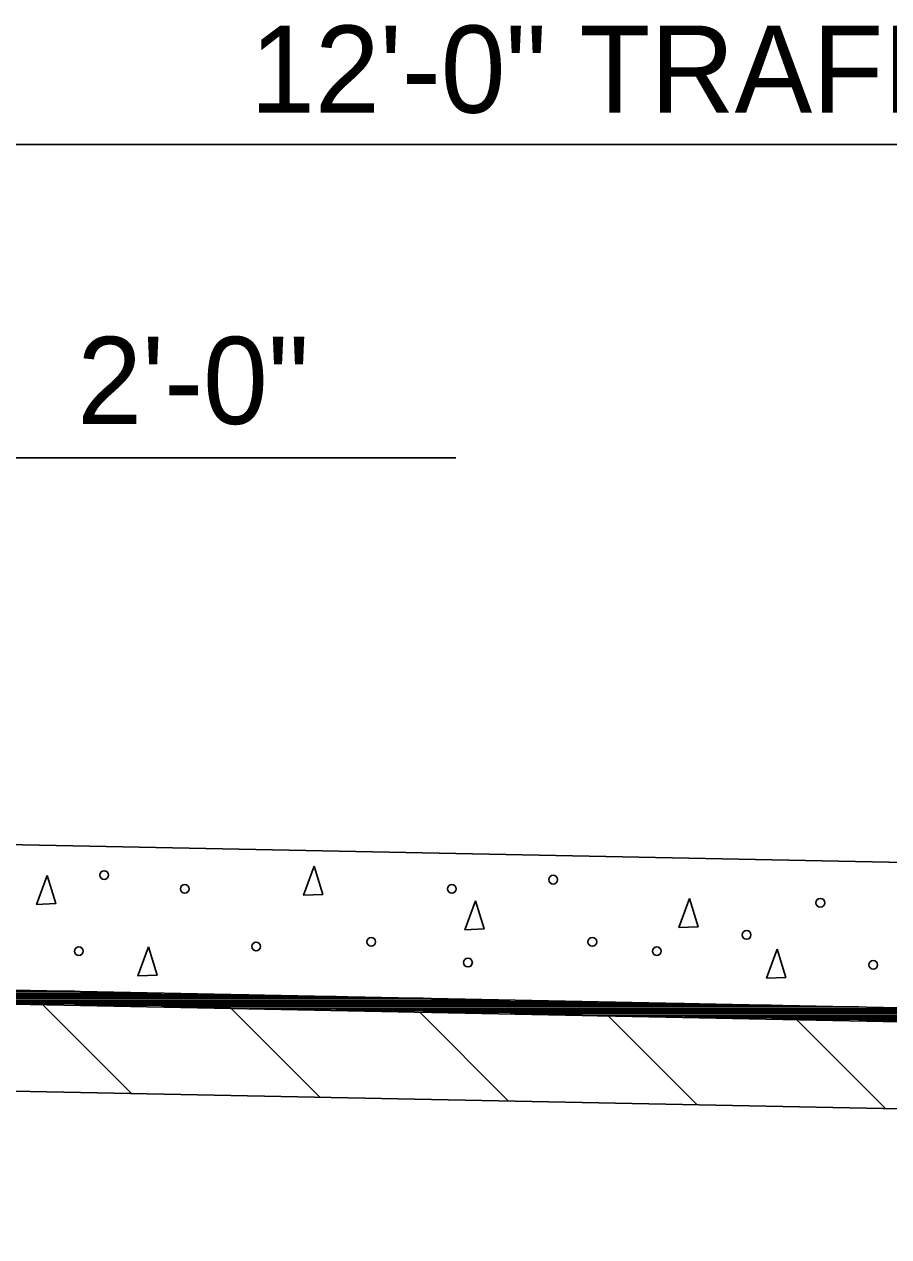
# Model space of a CAD drawing. Extents: x 60325 to 61047, y 53669 to 53767.
# Drawn here: x 60356.12 to 60361.08, y 53739.08 to 53746.03 of the extents above; entities that cross this region are included whole.
import ezdxf

# ---------------------------------------------------------------- set-up
doc = ezdxf.new("R2010")
doc.units = 0
doc.layers.add('R_Border', color=7, linetype='Continuous')
doc.layers.add('R_Border Prem', color=7, linetype='Continuous')

msp = doc.modelspace()

# ---------------------------------------------------------------- linework, layer by layer
at = {"layer": 'R_Border'}
for p, q in [((60367.2467, 53745.3445), (60355.2467, 53745.3445)), ((60358.5934, 53743.5486), (60355.2467, 53743.5486))]:
    msp.add_line(p, q, dxfattribs=at)
msp.add_lwpolyline([(60353.2158, 53741.2633), (60355.2467, 53741.3445), (60381.2467, 53740.8245)], dxfattribs=at)
at = {"layer": 'R_Border Prem'}
for p, q in [((60353.2467, 53740.468), (60357.4066, 53740.468)), ((60353.2467, 53740.458), (60357.9066, 53740.458)), ((60353.5868, 53740.478), (60356.9066, 53740.478)), ((60354.0868, 53740.488), (60356.4066, 53740.488)), ((60355.2467, 53740.5112), (60383.2467, 53739.9512)), ((60353.2467, 53740.448), (60358.4066, 53740.448)), ((60353.2467, 53740.438), (60358.9066, 53740.438)), ((60355.2467, 53740.4312), (60383.2467, 53739.8712)), ((60355.4058, 53740.428), (60359.4066, 53740.428)), ((60355.9058, 53740.418), (60359.9066, 53740.418)), ((60356.2223, 53740.4117), (60356.7326, 53739.9014)), ((60356.4058, 53740.408), (60360.4066, 53740.408)), ((60356.9058, 53740.398), (60360.9066, 53740.398)), ((60357.3046, 53740.39), (60357.8149, 53739.8797)), ((60357.4058, 53740.388), (60361.4066, 53740.388)), ((60357.9058, 53740.378), (60361.9066, 53740.378)), ((60358.3869, 53740.3684), (60358.8972, 53739.8581)), ((60358.4058, 53740.368), (60362.4066, 53740.368)), ((60358.9058, 53740.358), (60362.9066, 53740.358)), ((60359.4058, 53740.348), (60363.4066, 53740.348)), ((60359.4692, 53740.3467), (60359.9795, 53739.8364)), ((60359.9058, 53740.338), (60363.9066, 53740.338)), ((60360.4058, 53740.328), (60364.4066, 53740.328)), ((60360.5515, 53740.3251), (60361.0618, 53739.8148)), ((60360.9058, 53740.318), (60364.9066, 53740.318)), ((60355.2467, 53739.9311), (60397.7927, 53739.0802))]:
    msp.add_line(p, q, dxfattribs=at)
for points in [[(60356.2481, 53741.1523), (60356.1876, 53740.9863), (60356.2976, 53740.9908), (60356.2481, 53741.1523)], [(60357.7812, 53741.2051), (60357.7207, 53741.0391), (60357.8307, 53741.0436), (60357.7812, 53741.2051)], [(60359.9353, 53741.0201), (60359.8748, 53740.8541), (60359.9848, 53740.8586), (60359.9353, 53741.0201)], [(60358.7063, 53741.0069), (60358.6458, 53740.8409), (60358.7558, 53740.8454), (60358.7063, 53741.0069)], [(60356.8296, 53740.7426), (60356.7691, 53740.5766), (60356.8791, 53740.5811), (60356.8296, 53740.7426)], [(60360.4375, 53740.7294), (60360.377, 53740.5634), (60360.487, 53740.5679), (60360.4375, 53740.7294)]]:
    msp.add_lwpolyline(points, dxfattribs=at)
for centre in [(60356.5757, 53741.1547), (60359.1528, 53741.1283), (60357.0383, 53741.0754), (60358.5713, 53741.0754), (60360.6859, 53740.9961), (60360.263, 53740.8111), (60356.4304, 53740.7186), (60357.448, 53740.745), (60358.1088, 53740.7714), (60359.3775, 53740.7714), (60359.7475, 53740.7186), (60358.6638, 53740.6525), (60360.9898, 53740.6393)]:
    msp.add_circle(centre, 0.025, dxfattribs=at)

# ---------------------------------------------------------------- texts
at = {"layer": 'R_Border'}
for s, p in [('12\'-0" TRAFFIC LANE', (60357.4135, 53745.5271)), ('2\'-0"', (60356.4213, 53743.7418))]:
    msp.add_text(s, height=0.5, dxfattribs=at).set_placement(p)

doc.saveas('drawing.dxf')
